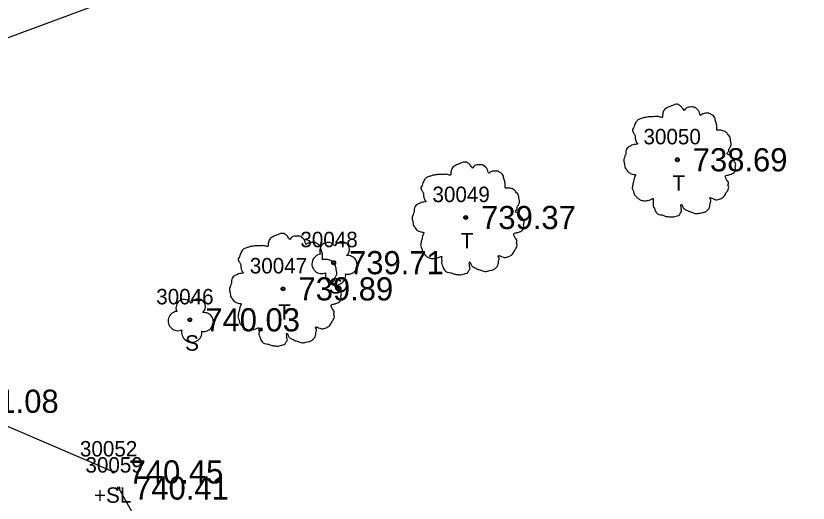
# Model space of a CAD drawing. Extents: x 1375131 to 1378678, y 999028 to 1004053.
# Drawn here: x 1376836.5 to 1376887.8, y 1002721.2 to 1002752.8 of the extents above; entities that cross this region are included whole.
import ezdxf

# ---------------------------------------------------------------- set-up
doc = ezdxf.new("R2010")
doc.units = 0
for name, color, linetype in [('RD_EX_Road', 7, 'Continuous'), ('RD_EX_RW', 7, 'Continuous'), ('RD_EX_TX_VEG_ELEV', 7, 'Continuous'), ('RD_EX_VEG', 7, 'Continuous'), ('RD_EX_VEG_txCode', 7, 'Continuous'), ('RD_HC_Cl', 7, 'Continuous'), ('RD_HC_Data', 7, 'Continuous'), ('RD_SMD_Locator', 7, 'Continuous')]:
    doc.layers.add(name, color=color, linetype=linetype)

msp = doc.modelspace()

# ---------------------------------------------------------------- linework, layer by layer
at = {"layer": 'RD_EX_Road'}
for points in [[(1377013.314, 1002264.907), (1376982.808, 1002315.683), (1376952.468, 1002370.341), (1376923.174, 1002424.32), (1376895.644, 1002480.03), (1376870.11, 1002535.049), (1376846.329, 1002588.864), (1376822.292, 1002645.031), (1376786.564, 1002736.458)], [(1376994.747, 1002253.913), (1376964.909, 1002306.463), (1376934.396, 1002359.987), (1376904.773, 1002415.485), (1376877.271, 1002471.511), (1376851.037, 1002526.893), (1376827.48, 1002581.62), (1376804.191, 1002637.821), (1376768.457, 1002728.838)]]:
    msp.add_spline(points, degree=3, dxfattribs=at)
at = {"layer": 'RD_EX_RW'}
msp.add_arc((1379404.86, 1003700.108), 2767, 200.269954, 211.131166, dxfattribs=at)
at = {"layer": 'RD_EX_VEG'}
msp.add_lwpolyline([(1376842.762, 1002723.226), (1376832.093, 1002727.803), (1376823.348, 1002720.418), (1376822.468, 1002711.668), (1376833.651, 1002706.033), (1376840.672, 1002709.675), (1376845.16, 1002718.521), (1376843.119, 1002722.182)], dxfattribs=at)
for centre, radius in [((1376879.328, 1002743.443), 0.125), ((1376879.322, 1002743.434), 0.00005), ((1376865.611, 1002739.702), 0.125), ((1376865.605, 1002739.693), 0.00005), ((1376857.05, 1002736.779), 0.125), ((1376853.771, 1002735.082), 0.125), ((1376853.765, 1002735.073), 0.00005), ((1376847.732, 1002733.078), 0.125)]:
    msp.add_circle(centre, radius, dxfattribs=at)
for centre, radius, start, end in [((1376856.689, 1002737.553), 0.542, 34.9763, 204.756), ((1376857.573, 1002737.63), 0.497, 308.7626, 152.0467), ((1376856.268, 1002736.701), 0.628, 96.4518, 294.734), ((1376857.97, 1002736.639), 0.609, 256.5667, 98.1046), ((1376857.173, 1002735.981), 0.659, 166.8827, 5.7589), ((1376847.371, 1002733.852), 0.542, 34.9763, 204.756), ((1376848.255, 1002733.929), 0.497, 308.7626, 152.0467), ((1376846.95, 1002733), 0.628, 96.4518, 294.734), ((1376848.652, 1002732.938), 0.609, 256.5667, 98.1046), ((1376847.855, 1002732.28), 0.659, 166.8827, 5.7589)]:
    msp.add_arc(centre, radius, start, end, dxfattribs=at)
for points in [[(1376879.394, 1002747.027), (1376879.244, 1002747.039), (1376879.082, 1002746.989), (1376878.957, 1002746.939), (1376878.844, 1002746.902), (1376878.732, 1002746.852), (1376878.582, 1002746.764), (1376878.469, 1002746.664), (1376878.407, 1002746.539), (1376878.382, 1002746.427), (1376878.357, 1002746.289), (1376878.357, 1002746.202), (1376878.294, 1002746.189), (1376878.219, 1002746.202), (1376878.095, 1002746.239), (1376877.97, 1002746.239), (1376877.845, 1002746.239), (1376877.67, 1002746.227), (1376877.495, 1002746.227), (1376877.357, 1002746.202), (1376877.195, 1002746.177), (1376877.008, 1002746.115), (1376876.833, 1002746.052), (1376876.683, 1002745.927), (1376876.558, 1002745.69), (1376876.495, 1002745.515), (1376876.42, 1002745.39), (1376876.495, 1002745.165), (1376876.583, 1002744.99), (1376876.595, 1002744.89), (1376876.633, 1002744.678), (1376876.683, 1002744.565), (1376876.745, 1002744.465), (1376876.708, 1002744.453), (1376876.52, 1002744.428), (1376876.37, 1002744.378), (1376876.158, 1002744.265), (1376876.045, 1002744.153), (1376875.995, 1002743.99), (1376875.983, 1002743.816), (1376875.933, 1002743.716), (1376875.896, 1002743.578), (1376875.883, 1002743.541), (1376875.858, 1002743.378), (1376875.908, 1002743.153), (1376875.921, 1002742.978), (1376875.983, 1002742.866), (1376876.058, 1002742.779), (1376876.145, 1002742.654), (1376876.345, 1002742.541), (1376876.508, 1002742.491), (1376876.608, 1002742.479), (1376876.52, 1002742.229), (1376876.495, 1002742.054), (1376876.433, 1002741.854), (1376876.433, 1002741.816), (1376876.408, 1002741.579), (1376876.483, 1002741.417), (1376876.52, 1002741.229), (1376876.608, 1002741.117), (1376876.745, 1002740.967), (1376876.908, 1002740.854), (1376877.157, 1002740.792), (1376877.357, 1002740.804), (1376877.645, 1002740.892), (1376877.77, 1002740.929), (1376877.757, 1002740.842), (1376877.77, 1002740.654), (1376877.77, 1002740.442), (1376877.845, 1002740.28), (1376877.895, 1002740.142), (1376877.97, 1002740.017), (1376878.132, 1002739.905), (1376878.332, 1002739.867), (1376878.544, 1002739.792), (1376878.769, 1002739.755), (1376879.019, 1002739.742), (1376879.319, 1002739.817), (1376879.456, 1002739.88), (1376879.506, 1002739.967), (1376879.606, 1002740.155), (1376879.581, 1002740.267), (1376879.594, 1002740.567), (1376879.644, 1002740.479), (1376879.731, 1002740.305), (1376879.981, 1002740.155), (1376880.181, 1002740.067), (1376880.419, 1002739.992), (1376880.568, 1002739.955), (1376880.806, 1002739.992), (1376880.993, 1002740.03), (1376881.181, 1002740.092), (1376881.331, 1002740.23), (1376881.418, 1002740.367), (1376881.443, 1002740.504), (1376881.481, 1002740.692), (1376881.506, 1002740.779)], [(1376881.506, 1002740.779), (1376881.468, 1002740.867), (1376881.443, 1002740.992), (1376881.481, 1002740.979), (1376881.568, 1002740.954), (1376881.705, 1002740.892), (1376881.818, 1002740.854), (1376881.98, 1002740.867), (1376882.118, 1002740.917), (1376882.343, 1002741.054), (1376882.48, 1002741.292), (1376882.618, 1002741.492), (1376882.655, 1002741.654), (1376882.63, 1002741.766), (1376882.618, 1002742.016), (1376882.518, 1002742.141), (1376882.493, 1002742.204), (1376882.443, 1002742.404), (1376882.48, 1002742.429), (1376882.618, 1002742.454), (1376882.805, 1002742.516), (1376882.942, 1002742.579), (1376883.055, 1002742.666), (1376883.092, 1002742.779), (1376883.08, 1002742.978), (1376883.105, 1002743.178), (1376883.067, 1002743.253), (1376883.017, 1002743.328), (1376882.98, 1002743.428), (1376882.905, 1002743.503), (1376882.855, 1002743.578), (1376882.805, 1002743.628), (1376882.743, 1002743.703), (1376882.655, 1002743.766), (1376882.58, 1002743.791), (1376882.555, 1002743.866), (1376882.63, 1002743.965), (1376882.655, 1002744.015), (1376882.668, 1002744.128), (1376882.78, 1002744.303), (1376882.805, 1002744.503), (1376882.78, 1002744.715), (1376882.755, 1002744.853), (1376882.68, 1002744.99), (1376882.58, 1002745.115), (1376882.518, 1002745.202), (1376882.43, 1002745.265), (1376882.268, 1002745.327), (1376882.143, 1002745.352), (1376881.968, 1002745.352), (1376881.868, 1002745.377), (1376881.88, 1002745.402), (1376881.88, 1002745.477), (1376881.88, 1002745.615), (1376881.843, 1002745.84), (1376881.768, 1002746.09), (1376881.768, 1002746.102), (1376881.718, 1002746.227), (1376881.606, 1002746.327), (1376881.518, 1002746.377), (1376881.418, 1002746.439), (1376881.293, 1002746.452), (1376881.143, 1002746.452), (1376881.006, 1002746.427), (1376880.906, 1002746.377), (1376880.818, 1002746.314), (1376880.781, 1002746.389), (1376880.731, 1002746.539), (1376880.706, 1002746.614), (1376880.631, 1002746.702), (1376880.519, 1002746.802), (1376880.294, 1002746.864), (1376879.981, 1002746.827), (1376879.831, 1002746.727), (1376879.756, 1002746.639), (1376879.731, 1002746.702), (1376879.631, 1002746.802), (1376879.581, 1002746.889), (1376879.494, 1002746.952), (1376879.419, 1002747.002), (1376879.369, 1002747.027)], [(1376865.677, 1002743.286), (1376865.527, 1002743.298), (1376865.365, 1002743.248), (1376865.24, 1002743.198), (1376865.127, 1002743.161), (1376865.015, 1002743.111), (1376864.865, 1002743.023), (1376864.752, 1002742.923), (1376864.69, 1002742.798), (1376864.665, 1002742.686), (1376864.64, 1002742.548), (1376864.64, 1002742.461), (1376864.577, 1002742.448), (1376864.502, 1002742.461), (1376864.378, 1002742.498), (1376864.253, 1002742.498), (1376864.128, 1002742.498), (1376863.953, 1002742.486), (1376863.778, 1002742.486), (1376863.64, 1002742.461), (1376863.478, 1002742.436), (1376863.291, 1002742.374), (1376863.116, 1002742.311), (1376862.966, 1002742.186), (1376862.841, 1002741.949), (1376862.778, 1002741.774), (1376862.703, 1002741.649), (1376862.778, 1002741.424), (1376862.866, 1002741.249), (1376862.878, 1002741.149), (1376862.916, 1002740.937), (1376862.966, 1002740.824), (1376863.028, 1002740.724), (1376862.991, 1002740.712), (1376862.803, 1002740.687), (1376862.653, 1002740.637), (1376862.441, 1002740.524), (1376862.328, 1002740.412), (1376862.278, 1002740.249), (1376862.266, 1002740.075), (1376862.216, 1002739.975), (1376862.179, 1002739.837), (1376862.166, 1002739.8), (1376862.141, 1002739.637), (1376862.191, 1002739.412), (1376862.204, 1002739.237), (1376862.266, 1002739.125), (1376862.341, 1002739.038), (1376862.428, 1002738.913), (1376862.628, 1002738.8), (1376862.791, 1002738.75), (1376862.891, 1002738.738), (1376862.803, 1002738.488), (1376862.778, 1002738.313), (1376862.716, 1002738.113), (1376862.716, 1002738.075), (1376862.691, 1002737.838), (1376862.766, 1002737.676), (1376862.803, 1002737.488), (1376862.891, 1002737.376), (1376863.028, 1002737.226), (1376863.191, 1002737.113), (1376863.44, 1002737.051), (1376863.64, 1002737.063), (1376863.928, 1002737.151), (1376864.053, 1002737.188), (1376864.04, 1002737.101), (1376864.053, 1002736.913), (1376864.053, 1002736.701), (1376864.128, 1002736.539), (1376864.178, 1002736.401), (1376864.253, 1002736.276), (1376864.415, 1002736.164), (1376864.615, 1002736.126), (1376864.827, 1002736.051), (1376865.052, 1002736.014), (1376865.302, 1002736.001), (1376865.602, 1002736.076), (1376865.739, 1002736.139), (1376865.789, 1002736.226), (1376865.889, 1002736.414), (1376865.864, 1002736.526), (1376865.877, 1002736.826), (1376865.927, 1002736.738), (1376866.014, 1002736.564), (1376866.264, 1002736.414), (1376866.464, 1002736.326), (1376866.702, 1002736.251), (1376866.851, 1002736.214), (1376867.089, 1002736.251), (1376867.276, 1002736.289), (1376867.464, 1002736.351), (1376867.614, 1002736.489), (1376867.701, 1002736.626), (1376867.726, 1002736.763), (1376867.764, 1002736.951), (1376867.789, 1002737.038)], [(1376867.789, 1002737.038), (1376867.751, 1002737.126), (1376867.726, 1002737.251), (1376867.764, 1002737.238), (1376867.851, 1002737.213), (1376867.988, 1002737.151), (1376868.101, 1002737.113), (1376868.263, 1002737.126), (1376868.401, 1002737.176), (1376868.626, 1002737.313), (1376868.763, 1002737.551), (1376868.901, 1002737.751), (1376868.938, 1002737.913), (1376868.913, 1002738.025), (1376868.901, 1002738.275), (1376868.801, 1002738.4), (1376868.776, 1002738.463), (1376868.726, 1002738.663), (1376868.763, 1002738.688), (1376868.901, 1002738.713), (1376869.088, 1002738.775), (1376869.225, 1002738.838), (1376869.338, 1002738.925), (1376869.375, 1002739.038), (1376869.363, 1002739.237), (1376869.388, 1002739.437), (1376869.35, 1002739.512), (1376869.3, 1002739.587), (1376869.263, 1002739.687), (1376869.188, 1002739.762), (1376869.138, 1002739.837), (1376869.088, 1002739.887), (1376869.026, 1002739.962), (1376868.938, 1002740.025), (1376868.863, 1002740.05), (1376868.838, 1002740.125), (1376868.913, 1002740.224), (1376868.938, 1002740.274), (1376868.951, 1002740.387), (1376869.063, 1002740.562), (1376869.088, 1002740.762), (1376869.063, 1002740.974), (1376869.038, 1002741.112), (1376868.963, 1002741.249), (1376868.863, 1002741.374), (1376868.801, 1002741.461), (1376868.713, 1002741.524), (1376868.551, 1002741.586), (1376868.426, 1002741.611), (1376868.251, 1002741.611), (1376868.151, 1002741.636), (1376868.163, 1002741.661), (1376868.163, 1002741.736), (1376868.163, 1002741.874), (1376868.126, 1002742.099), (1376868.051, 1002742.349), (1376868.051, 1002742.361), (1376868.001, 1002742.486), (1376867.889, 1002742.586), (1376867.801, 1002742.636), (1376867.701, 1002742.698), (1376867.576, 1002742.711), (1376867.426, 1002742.711), (1376867.289, 1002742.686), (1376867.189, 1002742.636), (1376867.101, 1002742.573), (1376867.064, 1002742.648), (1376867.014, 1002742.798), (1376866.989, 1002742.873), (1376866.914, 1002742.961), (1376866.802, 1002743.061), (1376866.577, 1002743.123), (1376866.264, 1002743.086), (1376866.114, 1002742.986), (1376866.039, 1002742.898), (1376866.014, 1002742.961), (1376865.914, 1002743.061), (1376865.864, 1002743.148), (1376865.777, 1002743.211), (1376865.702, 1002743.261), (1376865.652, 1002743.286)], [(1376853.837, 1002738.666), (1376853.687, 1002738.678), (1376853.525, 1002738.628), (1376853.4, 1002738.578), (1376853.287, 1002738.541), (1376853.175, 1002738.491), (1376853.025, 1002738.403), (1376852.912, 1002738.303), (1376852.85, 1002738.178), (1376852.825, 1002738.066), (1376852.8, 1002737.928), (1376852.8, 1002737.841), (1376852.737, 1002737.828), (1376852.662, 1002737.841), (1376852.538, 1002737.878), (1376852.413, 1002737.878), (1376852.288, 1002737.878), (1376852.113, 1002737.866), (1376851.938, 1002737.866), (1376851.8, 1002737.841), (1376851.638, 1002737.816), (1376851.451, 1002737.754), (1376851.276, 1002737.691), (1376851.126, 1002737.566), (1376851.001, 1002737.329), (1376850.938, 1002737.154), (1376850.863, 1002737.029), (1376850.938, 1002736.804), (1376851.026, 1002736.629), (1376851.038, 1002736.529), (1376851.076, 1002736.317), (1376851.126, 1002736.204), (1376851.188, 1002736.104), (1376851.151, 1002736.092), (1376850.963, 1002736.067), (1376850.813, 1002736.017), (1376850.601, 1002735.904), (1376850.488, 1002735.792), (1376850.438, 1002735.629), (1376850.426, 1002735.455), (1376850.376, 1002735.355), (1376850.339, 1002735.217), (1376850.326, 1002735.18), (1376850.301, 1002735.017), (1376850.351, 1002734.792), (1376850.364, 1002734.617), (1376850.426, 1002734.505), (1376850.501, 1002734.418), (1376850.588, 1002734.293), (1376850.788, 1002734.18), (1376850.951, 1002734.13), (1376851.051, 1002734.118), (1376850.963, 1002733.868), (1376850.938, 1002733.693), (1376850.876, 1002733.493), (1376850.876, 1002733.455), (1376850.851, 1002733.218), (1376850.926, 1002733.056), (1376850.963, 1002732.868), (1376851.051, 1002732.756), (1376851.188, 1002732.606), (1376851.351, 1002732.493), (1376851.6, 1002732.431), (1376851.8, 1002732.443), (1376852.088, 1002732.531), (1376852.213, 1002732.568), (1376852.2, 1002732.481), (1376852.213, 1002732.293), (1376852.213, 1002732.081), (1376852.288, 1002731.919), (1376852.338, 1002731.781), (1376852.413, 1002731.656), (1376852.575, 1002731.544), (1376852.775, 1002731.506), (1376852.987, 1002731.431), (1376853.212, 1002731.394), (1376853.462, 1002731.381), (1376853.762, 1002731.456), (1376853.899, 1002731.519), (1376853.949, 1002731.606), (1376854.049, 1002731.794), (1376854.024, 1002731.906), (1376854.037, 1002732.206), (1376854.087, 1002732.118), (1376854.174, 1002731.944), (1376854.424, 1002731.794), (1376854.624, 1002731.706), (1376854.862, 1002731.631), (1376855.011, 1002731.594), (1376855.249, 1002731.631), (1376855.436, 1002731.669), (1376855.624, 1002731.731), (1376855.774, 1002731.869), (1376855.861, 1002732.006), (1376855.886, 1002732.143), (1376855.924, 1002732.331), (1376855.949, 1002732.418)], [(1376855.949, 1002732.418), (1376855.911, 1002732.506), (1376855.886, 1002732.631), (1376855.924, 1002732.618), (1376856.011, 1002732.593), (1376856.148, 1002732.531), (1376856.261, 1002732.493), (1376856.423, 1002732.506), (1376856.561, 1002732.556), (1376856.786, 1002732.693), (1376856.923, 1002732.931), (1376857.061, 1002733.131), (1376857.098, 1002733.293), (1376857.073, 1002733.405), (1376857.061, 1002733.655), (1376856.961, 1002733.78), (1376856.936, 1002733.843), (1376856.886, 1002734.043), (1376856.923, 1002734.068), (1376857.061, 1002734.093), (1376857.248, 1002734.155), (1376857.385, 1002734.218), (1376857.498, 1002734.305), (1376857.535, 1002734.418), (1376857.523, 1002734.617), (1376857.548, 1002734.817), (1376857.51, 1002734.892), (1376857.46, 1002734.967), (1376857.423, 1002735.067), (1376857.348, 1002735.142), (1376857.298, 1002735.217), (1376857.248, 1002735.267), (1376857.186, 1002735.342), (1376857.098, 1002735.405), (1376857.023, 1002735.43), (1376856.998, 1002735.505), (1376857.073, 1002735.604), (1376857.098, 1002735.654), (1376857.111, 1002735.767), (1376857.223, 1002735.942), (1376857.248, 1002736.142), (1376857.223, 1002736.354), (1376857.198, 1002736.492), (1376857.123, 1002736.629), (1376857.023, 1002736.754), (1376856.961, 1002736.841), (1376856.873, 1002736.904), (1376856.711, 1002736.966), (1376856.586, 1002736.991), (1376856.411, 1002736.991), (1376856.311, 1002737.016), (1376856.323, 1002737.041), (1376856.323, 1002737.116), (1376856.323, 1002737.254), (1376856.286, 1002737.479), (1376856.211, 1002737.729), (1376856.211, 1002737.741), (1376856.161, 1002737.866), (1376856.049, 1002737.966), (1376855.961, 1002738.016), (1376855.861, 1002738.078), (1376855.736, 1002738.091), (1376855.586, 1002738.091), (1376855.449, 1002738.066), (1376855.349, 1002738.016), (1376855.261, 1002737.953), (1376855.224, 1002738.028), (1376855.174, 1002738.178), (1376855.149, 1002738.253), (1376855.074, 1002738.341), (1376854.962, 1002738.441), (1376854.737, 1002738.503), (1376854.424, 1002738.466), (1376854.274, 1002738.366), (1376854.199, 1002738.278), (1376854.174, 1002738.341), (1376854.074, 1002738.441), (1376854.024, 1002738.528), (1376853.937, 1002738.591), (1376853.862, 1002738.641), (1376853.812, 1002738.666)]]:
    msp.add_spline(points, degree=3, dxfattribs=at)
at = {"layer": 'RD_HC_Cl'}
msp.add_arc((1379404.86, 1003700.108), 2800, 200.269954, 211.131166, dxfattribs=at)
at = {"layer": 'RD_HC_Data'}
msp.add_line((1376778.262, 1002730.065), (1376911.622, 1002779.317), dxfattribs=at)
at = {"layer": 'RD_SMD_Locator'}
for centre in [(1376879.328, 1002743.443), (1376865.611, 1002739.702), (1376857.05, 1002736.779), (1376853.771, 1002735.082), (1376847.732, 1002733.078), (1376842.762, 1002723.226), (1376843.119, 1002722.182)]:
    msp.add_circle(centre, 0.075, dxfattribs=at)

# ---------------------------------------------------------------- texts
at = {"layer": 'RD_EX_TX_VEG_ELEV'}
for s, p in [('738.69', (1376880.328, 1002742.693)), ('739.37', (1376866.611, 1002738.952)), ('739.71', (1376858.05, 1002736.029)), ('739.89', (1376854.771, 1002734.332)), ('740.03', (1376848.732, 1002732.328)), ('741.08', (1376833.093, 1002727.053)), ('740.45', (1376843.762, 1002722.476)), ('740.41', (1376844.119, 1002721.432))]:
    msp.add_text(s, height=1.5, dxfattribs=at).set_placement(p)
at = {"layer": 'RD_EX_VEG_txCode'}
for s, p in [('30050', (1376877.131, 1002744.443)), ('T', (1376879.005, 1002741.443)), ('30049', (1376863.454, 1002740.702)), ('30048', (1376854.893, 1002737.779)), ('T', (1376865.288, 1002737.702)), ('30047', (1376851.614, 1002736.082)), ('S', (1376856.743, 1002734.779)), ('30046', (1376845.551, 1002734.078)), ('T', (1376853.448, 1002733.082)), ('S', (1376847.425, 1002731.078)), ('30052', (1376840.605, 1002724.226)), ('30059', (1376840.962, 1002723.182)), ('+SL', (1376841.518, 1002721.226))]:
    msp.add_text(s, height=1, dxfattribs=at).set_placement(p)

doc.saveas('drawing.dxf')
